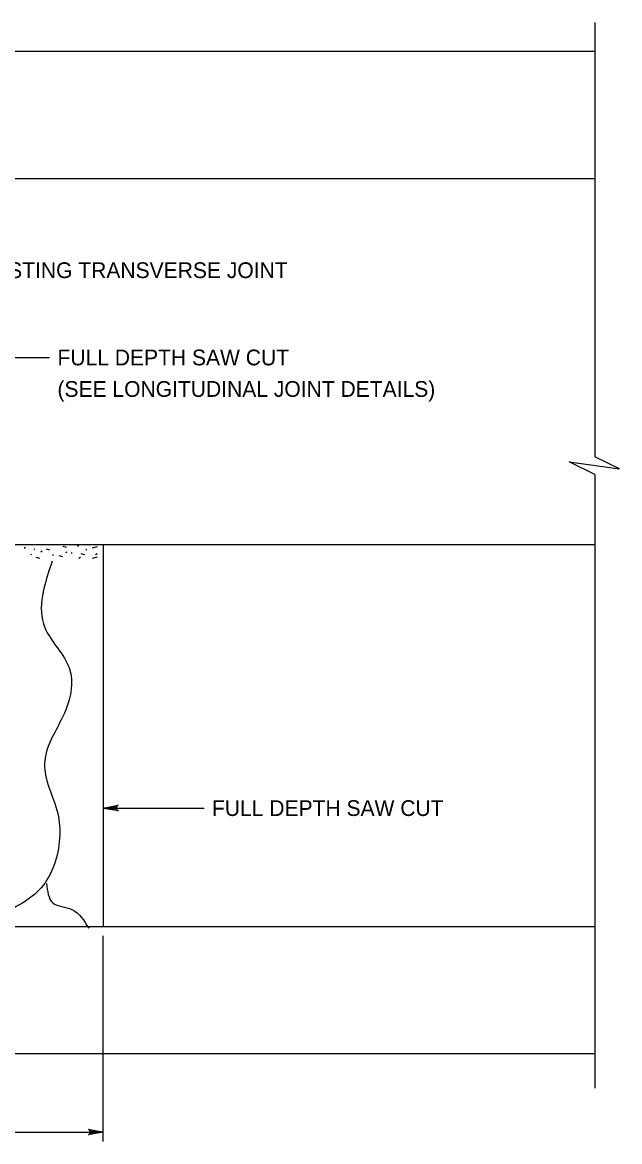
# Model space of a CAD drawing. Extents: x 1.45 to 8.06, y 0.17 to 9.98.
# Drawn here: x 4.954 to 7.23, y 5.712 to 9.976 of the extents above; entities that cross this region are included whole.
import ezdxf

# ---------------------------------------------------------------- set-up
doc = ezdxf.new("R2010")
doc.units = 0
for name, color, linetype in [('DETL-DIMS', 7, 'Continuous'), ('DETL-LINE', 7, 'Continuous'), ('DETL-NOTE', 7, 'Continuous'), ('DETL-PATT', 7, 'Continuous')]:
    doc.layers.add(name, color=color, linetype=linetype)

msp = doc.modelspace()

# ---------------------------------------------------------------- linework, layer by layer
at = {"layer": 'DETL-DIMS'}
for p, q in [((4.6853, 8.6995), (5.057, 8.6995)), ((5.2619, 6.9829), (5.646, 6.9829)), ((5.2619, 6.9829), (5.646, 6.9829)), ((5.2619, 5.7125), (5.2619, 6.4968)), ((5.2619, 5.7125), (5.2619, 6.4968)), ((3.4438, 5.7487), (5.2619, 5.7487)), ((3.4438, 5.7487), (5.2619, 5.7487))]:
    msp.add_line(p, q, dxfattribs=at)
for points in [[(5.2619, 6.9829), (5.3184, 6.9935), (5.3141, 6.9905), (5.3118, 6.9867), (5.3112, 6.9829), (5.3118, 6.9791), (5.3141, 6.9753), (5.3184, 6.9723), (5.2619, 6.9829), (5.3141, 6.9753), (5.3118, 6.9791), (5.2619, 6.9829), (5.3112, 6.9829), (5.3118, 6.9867), (5.2619, 6.9829), (5.3141, 6.9905)], [(5.2619, 6.9829), (5.3184, 6.9935), (5.3141, 6.9905), (5.3118, 6.9867), (5.3112, 6.9829), (5.3118, 6.9791), (5.3141, 6.9753), (5.3184, 6.9723), (5.2619, 6.9829), (5.3141, 6.9753), (5.3118, 6.9791), (5.2619, 6.9829), (5.3112, 6.9829), (5.3118, 6.9867), (5.2619, 6.9829), (5.3141, 6.9905)], [(5.2619, 5.7487), (5.2055, 5.7381), (5.2098, 5.7411), (5.212, 5.7449), (5.2127, 5.7487), (5.212, 5.7525), (5.2098, 5.7563), (5.2055, 5.7593), (5.2619, 5.7487), (5.2098, 5.7563), (5.212, 5.7525), (5.2619, 5.7487), (5.2127, 5.7487), (5.212, 5.7449), (5.2619, 5.7487), (5.2098, 5.7411)], [(5.2619, 5.7487), (5.2055, 5.7381), (5.2098, 5.7411), (5.212, 5.7449), (5.2127, 5.7487), (5.212, 5.7525), (5.2098, 5.7563), (5.2055, 5.7593), (5.2619, 5.7487), (5.2098, 5.7563), (5.212, 5.7525), (5.2619, 5.7487), (5.2127, 5.7487), (5.212, 5.7449), (5.2619, 5.7487), (5.2098, 5.7411)]]:
    msp.add_lwpolyline(points, dxfattribs=at)
at = {"layer": 'DETL-LINE'}
for p, q in [((7.1352, 9.9759), (7.1352, 8.3206)), ((1.5705, 9.8658), (7.1352, 9.8658)), ((1.5705, 9.381), (7.1352, 9.381)), ((7.1352, 8.254), (7.1352, 5.9166)), ((1.5705, 7.987), (7.1352, 7.987)), ((5.2619, 7.987), (5.2619, 6.5325)), ((5.2619, 7.9264), (5.2619, 7.9264)), ((3.4438, 6.5325), (5.2619, 6.5325)), ((5.2619, 6.5325), (7.1352, 6.5325)), ((1.5705, 6.0476), (7.1352, 6.0476))]:
    msp.add_line(p, q, dxfattribs=at)
msp.add_lwpolyline([(7.1352, 8.254), (7.0378, 8.3016), (7.23, 8.2755), (7.1352, 8.3206)], dxfattribs=at)
for points in [[(5.0671, 7.9238), (5.0387, 7.6711), (5.1332, 7.5128), (5.119, 7.3569), (5.0387, 7.1608), (5.0387, 7.1301), (5.0883, 6.9624), (5.0954, 6.8679), (5.0246, 6.679), (4.864, 6.575)], [(5.0458, 6.6955), (5.0694, 6.6223), (5.1426, 6.5963), (5.2063, 6.5254)]]:
    msp.add_spline(points, degree=3, dxfattribs=at)
at = {"layer": 'DETL-PATT'}
for p, q in [((4.9604, 7.9728), (4.966, 7.9765)), ((5.1078, 7.9803), (5.1209, 7.9765)), ((5.1638, 7.9803), (5.1694, 7.984)), ((5.2384, 7.9784), (5.2198, 7.9728)), ((4.9847, 7.9504), (4.9884, 7.9485)), ((4.9977, 7.9709), (5.0015, 7.9691)), ((5.0052, 7.9392), (5.0183, 7.9355)), ((5.0239, 7.9597), (5.0295, 7.9635)), ((5.0444, 7.9709), (5.0574, 7.9672)), ((5.0686, 7.9485), (5.0724, 7.9467)), ((5.0929, 7.9448), (5.106, 7.9411)), ((5.119, 7.956), (5.1246, 7.9597)), ((5.1395, 7.956), (5.1433, 7.9541)), ((5.1694, 7.9355), (5.175, 7.9392)), ((5.1769, 7.9523), (5.1899, 7.9485)), ((5.1955, 7.9691), (5.1992, 7.9672)), ((5.2384, 7.9392), (5.2198, 7.9336)), ((5.2328, 7.9485), (5.2384, 7.9523))]:
    msp.add_line(p, q, dxfattribs=at)

# ---------------------------------------------------------------- texts
at = {"layer": 'DETL-NOTE'}
for s, p in [('EXISTING TRANSVERSE JOINT', (4.7699, 9.0019)), ('FULL DEPTH SAW CUT', (5.0873, 8.6695)), ('(SEE LONGITUDINAL JOINT DETAILS)', (5.0873, 8.5495)), ('FULL DEPTH SAW CUT', (5.6763, 6.9529))]:
    msp.add_text(s, height=0.06, dxfattribs=at).set_placement(p)

doc.saveas('drawing.dxf')
